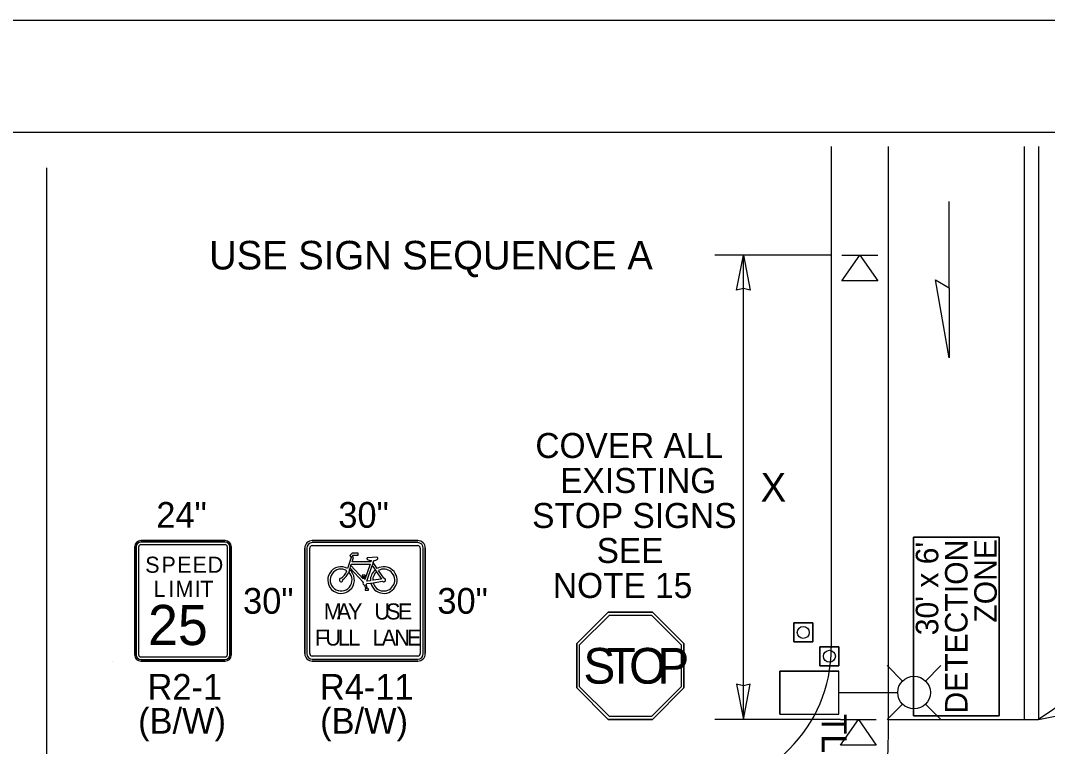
# Model space of a CAD drawing. Extents: x 99979.8 to 100075.7, y 99995 to 100010.7.
# Drawn here: x 100045.178 to 100048.053, y 100008.655 to 100010.687 of the extents above; entities that cross this region are included whole.
import ezdxf

# ---------------------------------------------------------------- set-up
doc = ezdxf.new("R2010")
doc.units = 0
for name, color, linetype in [('RD_ED_ShoulderPavedEdge', 7, 'Continuous'), ('RD_MK_LineDblYellowCenter', 7, 'Continuous'), ('RD_MK_LineEdgeWhite', 7, 'Continuous'), ('RD_MK_LineEdgeWhiteNew', 7, 'Continuous'), ('RD_MK_LineStop', 7, 'Continuous'), ('SH_GI_PlotLimits', 7, 'Continuous'), ('SH_GI_SheetBorder', 7, 'Continuous'), ('TR_SN_ConstructionSigns', 7, 'Continuous'), ('TR_WZ_PortableLightStandard', 7, 'Continuous'), ('TR_WZ_PortableSignMountBlk-Org', 7, 'Continuous'), ('TR_WZ_PortableSignMountBlk-Wht', 7, 'Continuous'), ('TR_WZ_TrafficCone', 7, 'Continuous'), ('TR_WZ_WorkZoneDetails', 7, 'Continuous'), ('TR_WZ_WorkZoneTextCurrent', 7, 'Continuous')]:
    doc.layers.add(name, color=color, linetype=linetype)

msp = doc.modelspace()

# ---------------------------------------------------------------- linework, layer by layer
at = {"layer": 'RD_ED_ShoulderPavedEdge'}
msp.add_lwpolyline([(100047.4475, 100010.335), (100047.4475, 100008.9304)], dxfattribs=at)
msp.add_arc((100047.0475, 100008.9304), 0.4, 270, 0, dxfattribs=at)
at = {"layer": 'RD_MK_LineDblYellowCenter'}
for p, q in [((100047.9875, 100010.335), (100047.9875, 100008.7304)), ((100048.0275, 100010.335), (100048.0275, 100008.7304))]:
    msp.add_line(p, q, dxfattribs=at)
at = {"layer": 'RD_MK_LineEdgeWhite'}
for p, q in [((100047.6075, 100008.9304), (100047.6075, 100010.335)), ((100047.6075, 100008.6904), (100047.6075, 100008.9304))]:
    msp.add_line(p, q, dxfattribs=at)
at = {"layer": 'RD_MK_LineEdgeWhiteNew'}
msp.add_arc((100046.1076, 100008.6984), 1.5, 277.2601, 359.6954, dxfattribs=at)
at = {"layer": 'RD_MK_LineStop'}
msp.add_line((100047.6075, 100008.7304), (100048.0275, 100008.7304), dxfattribs=at)
at = {"layer": 'SH_GI_PlotLimits'}
msp.add_lwpolyline([(100039.0625, 99999.6875), (100056.0625, 99999.6875), (100056.0625, 100010.6875), (100039.0625, 100010.6875)], close=True, dxfattribs=at)
at = {"layer": 'SH_GI_SheetBorder'}
msp.add_line((100040, 100010.375), (100055.75, 100010.375), dxfattribs=at)
at = {"layer": 'TR_SN_ConstructionSigns'}
for p, q in [((100045.5142, 100009.231), (100045.7505, 100009.231)), ((100045.7505, 100009.231), (100045.5142, 100009.231)), ((100045.7505, 100009.231), (100045.5142, 100009.231)), ((100045.7505, 100009.2268), (100045.5142, 100009.2268)), ((100045.9944, 100009.231), (100046.2897, 100009.231)), ((100046.2897, 100009.231), (100045.9944, 100009.231)), ((100046.2897, 100009.231), (100045.9944, 100009.231)), ((100046.2897, 100009.2254), (100045.9944, 100009.2254)), ((100045.4973, 100008.9104), (100045.4973, 100009.2141)), ((100045.4973, 100009.2141), (100045.4973, 100008.9104)), ((100045.4973, 100009.2141), (100045.4973, 100008.9104)), ((100045.5016, 100009.2141), (100045.5016, 100008.9104)), ((100045.5086, 100008.9104), (100045.5086, 100009.2141)), ((100045.5142, 100009.2198), (100045.7505, 100009.2198)), ((100045.7561, 100009.2141), (100045.7561, 100008.9104)), ((100045.7631, 100008.9104), (100045.7631, 100009.2141)), ((100045.7673, 100009.2141), (100045.7673, 100008.9104)), ((100045.7673, 100008.9104), (100045.7673, 100009.2141)), ((100045.7673, 100008.9104), (100045.7673, 100009.2141)), ((100045.9733, 100008.9146), (100045.9733, 100009.2099)), ((100045.9733, 100009.2099), (100045.9733, 100008.9146)), ((100045.9733, 100009.2099), (100045.9733, 100008.9146)), ((100045.9789, 100009.2099), (100045.9789, 100008.9146)), ((100045.9873, 100008.9146), (100045.9873, 100009.2099)), ((100045.9944, 100009.217), (100046.2897, 100009.217)), ((100046.106, 100009.1959), (100046.0991, 100009.1889)), ((100046.1225, 100009.1959), (100046.106, 100009.1959)), ((100046.1225, 100009.1904), (100046.1225, 100009.1959)), ((100046.2967, 100009.2099), (100046.2967, 100008.9146)), ((100046.3051, 100008.9146), (100046.3051, 100009.2099)), ((100046.3108, 100009.2099), (100046.3108, 100008.9146)), ((100046.3108, 100008.9146), (100046.3108, 100009.2099)), ((100046.3108, 100008.9146), (100046.3108, 100009.2099)), ((100046.1037, 100009.1842), (100046.0933, 100009.1531)), ((100046.0991, 100009.1889), (100046.1037, 100009.1842)), ((100046.1025, 100009.1614), (100046.1037, 100009.1652)), ((100046.1037, 100009.1652), (100046.1564, 100009.1652)), ((100046.1059, 100009.1717), (100046.1101, 100009.1842)), ((100046.1586, 100009.1717), (100046.1059, 100009.1717)), ((100046.1061, 100009.1882), (100046.1083, 100009.1904)), ((100046.1101, 100009.1842), (100046.1061, 100009.1882)), ((100046.1083, 100009.1904), (100046.1225, 100009.1904)), ((100046.1564, 100009.1652), (100046.1419, 100009.1219)), ((100046.1744, 100009.1846), (100046.1495, 100009.183)), ((100046.1597, 100009.1751), (100046.1586, 100009.1717)), ((100046.1647, 100009.1694), (100046.1621, 100009.1616)), ((100046.1647, 100009.1694), (100046.1667, 100009.1752)), ((100046.1759, 100009.1529), (100046.1647, 100009.1694)), ((100046.0985, 100009.1496), (100046.0963, 100009.1428)), ((100046.0985, 100009.1496), (100046.1001, 100009.1542)), ((100046.1001, 100009.1542), (100046.1025, 100009.1614)), ((100046.1001, 100009.1542), (100046.1367, 100009.1145)), ((100046.1371, 100009.1237), (100046.1025, 100009.1614)), ((100046.1424, 100009.1344), (100046.1336, 100009.1344)), ((100046.1424, 100009.1311), (100046.1424, 100009.1344)), ((100046.1474, 100009.1173), (100046.1621, 100009.1616)), ((100046.1621, 100009.1616), (100046.1705, 100009.1492)), ((100046.1705, 100009.1492), (100046.1742, 100009.1437)), ((100046.1742, 100009.1437), (100046.188, 100009.1234)), ((100046.1945, 100009.1256), (100046.1796, 100009.1475)), ((100046.1358, 100009.1311), (100046.1371, 100009.1237)), ((100046.1419, 100009.1219), (100046.1402, 100009.1311)), ((100046.1402, 100009.1311), (100046.1424, 100009.1311)), ((100046.141, 100009.1064), (100046.1446, 100009.0956)), ((100046.1493, 100009.0956), (100046.1452, 100009.1077)), ((100046.1469, 100009.1106), (100046.1582, 100009.1123)), ((100046.1573, 100009.1188), (100046.1474, 100009.1173)), ((100046.1582, 100009.1123), (100046.1647, 100009.1132)), ((100046.188, 100009.1234), (100046.1638, 100009.1198)), ((100046.1647, 100009.1132), (100046.191, 100009.1171)), ((100046.1446, 100009.0956), (100046.1428, 100009.0956)), ((100046.1428, 100009.0956), (100046.1428, 100009.0923)), ((100046.1428, 100009.0923), (100046.1516, 100009.0923)), ((100046.1516, 100009.0956), (100046.1493, 100009.0956)), ((100046.1516, 100009.0923), (100046.1516, 100009.0956)), ((100046.8229, 100009.0304), (100046.735, 100008.9426)), ((100046.8229, 100009.0304), (100046.735, 100008.9426)), ((100046.7428, 100008.9393), (100046.8261, 100009.0226)), ((100046.9472, 100009.0304), (100046.8229, 100009.0304)), ((100046.9472, 100009.0304), (100046.8229, 100009.0304)), ((100046.8261, 100009.0226), (100046.9439, 100009.0226)), ((100046.9439, 100009.0226), (100047.0272, 100008.9393)), ((100047.035, 100008.9426), (100046.9472, 100009.0304)), ((100047.035, 100008.9426), (100046.9472, 100009.0304)), ((100046.735, 100008.9426), (100046.735, 100008.8183)), ((100046.735, 100008.9426), (100046.735, 100008.8183)), ((100046.7428, 100008.8216), (100046.7428, 100008.9393)), ((100047.0272, 100008.9393), (100047.0272, 100008.8216)), ((100047.035, 100008.8183), (100047.035, 100008.9426)), ((100047.035, 100008.8183), (100047.035, 100008.9426)), ((100045.7505, 100008.9048), (100045.5142, 100008.9048)), ((100046.2897, 100008.9076), (100045.9944, 100008.9076)), ((100045.5142, 100008.8977), (100045.7505, 100008.8977)), ((100045.7505, 100008.8935), (100045.5142, 100008.8935)), ((100045.5142, 100008.8935), (100045.7505, 100008.8935)), ((100045.5142, 100008.8935), (100045.7505, 100008.8935)), ((100045.9944, 100008.8991), (100046.2897, 100008.8991)), ((100046.2897, 100008.8935), (100045.9944, 100008.8935)), ((100045.9944, 100008.8935), (100046.2897, 100008.8935)), ((100045.9944, 100008.8935), (100046.2897, 100008.8935)), ((100046.735, 100008.8183), (100046.8229, 100008.7304)), ((100046.735, 100008.8183), (100046.8229, 100008.7304)), ((100046.8261, 100008.7383), (100046.7428, 100008.8216)), ((100047.0272, 100008.8216), (100046.9439, 100008.7383)), ((100046.9472, 100008.7304), (100047.035, 100008.8183)), ((100046.9472, 100008.7304), (100047.035, 100008.8183)), ((100046.9439, 100008.7383), (100046.8261, 100008.7383)), ((100046.8229, 100008.7304), (100046.9472, 100008.7304)), ((100046.8229, 100008.7304), (100046.9472, 100008.7304))]:
    msp.add_line(p, q, dxfattribs=at)
for points in [[(100046.1336, 100009.1344), (100046.1336, 100009.1311), (100046.1358, 100009.1311)], [(100046.8229, 100009.0304), (100046.9472, 100009.0304), (100047.035, 100008.9426), (100047.035, 100008.8183), (100046.9472, 100008.7304), (100046.8229, 100008.7304), (100046.735, 100008.8183), (100046.735, 100008.9426), (100046.8229, 100009.0304)]]:
    msp.add_lwpolyline(points, dxfattribs=at)
for centre, radius, start, end in [((100045.5142, 100009.2141), 0.0169, 90, 180), ((100045.5142, 100009.2141), 0.0169, 90, 180), ((100045.5142, 100009.2141), 0.0169, 90, 180), ((100045.5142, 100009.2141), 0.0127, 90, 180), ((100045.7505, 100009.2141), 0.0169, 0, 90), ((100045.7505, 100009.2141), 0.0169, 0, 90), ((100045.7505, 100009.2141), 0.0169, 0, 90), ((100045.7505, 100009.2141), 0.0127, 0, 90), ((100045.9944, 100009.2099), 0.0211, 90, 180), ((100045.9944, 100009.2099), 0.0211, 90, 180), ((100045.9944, 100009.2099), 0.0211, 90, 180), ((100045.9944, 100009.2099), 0.0155, 90, 180), ((100046.2897, 100009.2099), 0.0211, 0, 90), ((100046.2897, 100009.2099), 0.0211, 0, 90), ((100046.2897, 100009.2099), 0.0211, 0, 90), ((100046.2897, 100009.2099), 0.0155, 0, 90), ((100045.5142, 100009.2141), 0.00562, 90, 180), ((100045.7505, 100009.2141), 0.00562, 0, 90), ((100045.9944, 100009.2099), 0.00703, 90, 180), ((100046.2897, 100009.2099), 0.00703, 0, 90), ((100046.1495, 100009.1808), 0.00219, 89.3854, 243.6828), ((100046.1747, 100009.1814), 0.00329, 294.5519, 96.4128), ((100046.075, 100009.1206), 0.0373, 60.5529, 50.868), ((100046.075, 100009.1206), 0.0307, 58.1532, 46.1649), ((100046.1945, 100009.1206), 0.0373, 130.0889, 182.8379), ((100046.1945, 100009.1206), 0.0373, 192.9622, 119.9648), ((100046.1945, 100009.1206), 0.0307, 131.3616, 181.6359), ((100046.1945, 100009.1206), 0.0307, 193.937, 119.0598), ((100046.075, 100009.1206), 0.00493, 105.257, 14.3233), ((100046.1415, 100009.1118), 0.00548, 151.1744, 264.8566), ((100046.1415, 100009.1118), 0.00548, 312.0053, 347.2932), ((100046.1945, 100009.1206), 0.00493, 225.1095, 90.4672), ((100045.5142, 100008.9104), 0.0169, 180, 270), ((100045.5142, 100008.9104), 0.0169, 180, 270), ((100045.5142, 100008.9104), 0.0169, 180, 270), ((100045.5142, 100008.9104), 0.0127, 180, 270), ((100045.5142, 100008.9104), 0.00562, 180, 270), ((100045.7505, 100008.9104), 0.0169, 270, 0), ((100045.7505, 100008.9104), 0.0169, 270, 0), ((100045.7505, 100008.9104), 0.0127, 270, 0), ((100045.7505, 100008.9104), 0.00562, 270, 0), ((100045.7505, 100008.9104), 0.0169, 270, 0), ((100045.9944, 100008.9146), 0.0211, 180, 270), ((100045.9944, 100008.9146), 0.0211, 180, 270), ((100045.9944, 100008.9146), 0.0211, 180, 270), ((100045.9944, 100008.9146), 0.0155, 180, 270), ((100045.9944, 100008.9146), 0.00703, 180, 270), ((100046.2897, 100008.9146), 0.0211, 270, 0), ((100046.2897, 100008.9146), 0.0211, 270, 0), ((100046.2897, 100008.9146), 0.0155, 270, 0), ((100046.2897, 100008.9146), 0.00703, 270, 0), ((100046.2897, 100008.9146), 0.0211, 270, 0)]:
    msp.add_arc(centre, radius, start, end, dxfattribs=at)
for centre, major_axis, ratio, start_param, end_param in [((100046.1627, 100009.1859), (-0.0186, 0), 0.588235, 0.686048, 1.410588), ((100046.1627, 100009.1859), (-0.0186, 0), 0.588235, 1.786993, 2.401245), ((100046.0799, 100009.1414), (-0.0105, -0.0158), 0.413554, 0.494612, 2.170849), ((100046.0799, 100009.1414), (-0.014, -0.021), 0.55814, 0.868091, 1.989998)]:
    msp.add_ellipse(centre, major_axis=major_axis, ratio=ratio, start_param=start_param, end_param=end_param, dxfattribs=at)
at = {"layer": 'TR_WZ_PortableLightStandard'}
for p, q in [((100047.6468, 100008.8378), (100047.6037, 100008.8809)), ((100047.7115, 100008.8378), (100047.7546, 100008.8809)), ((100047.303, 100008.8654), (100047.469, 100008.8654)), ((100047.303, 100008.7454), (100047.303, 100008.8654)), ((100047.469, 100008.8654), (100047.303, 100008.8654)), ((100047.469, 100008.7454), (100047.469, 100008.8654)), ((100047.469, 100008.8054), (100047.6334, 100008.8054)), ((100047.6468, 100008.773), (100047.6037, 100008.7301)), ((100047.7115, 100008.773), (100047.7546, 100008.7301)), ((100047.303, 100008.7454), (100047.469, 100008.7454)), ((100047.303, 100008.7454), (100047.469, 100008.7454))]:
    msp.add_line(p, q, dxfattribs=at)
for points in [[(100047.303, 100008.8654), (100047.303, 100008.8054), (100047.303, 100008.7454)], [(100047.469, 100008.7454), (100047.469, 100008.8054), (100047.469, 100008.8654)]]:
    msp.add_lwpolyline(points, dxfattribs=at)
msp.add_circle((100047.6792, 100008.8055), 0.0457, dxfattribs=at)
msp.add_circle((100047.6792, 100008.8055), 0.0457, dxfattribs=at)
at = {"layer": 'TR_WZ_PortableSignMountBlk-Org'}
msp.add_line((100047.4775, 100010.0304), (100047.5775, 100010.0304), dxfattribs=at)
msp.add_lwpolyline([(100047.5274, 100010.0304), (100047.5775, 100009.9586), (100047.4775, 100009.9586)], close=True, dxfattribs=at)
at = {"layer": 'TR_WZ_PortableSignMountBlk-Wht'}
msp.add_line((100047.4734, 100008.7304), (100047.5734, 100008.7304), dxfattribs=at)
msp.add_lwpolyline([(100047.5233, 100008.7304), (100047.5734, 100008.6586), (100047.4734, 100008.6586)], close=True, dxfattribs=at)
at = {"layer": 'TR_WZ_TrafficCone'}
for points in [[(100047.3956, 100009.0004), (100047.3956, 100008.9471), (100047.3423, 100008.9471), (100047.3423, 100009.0004), (100047.3956, 100009.0004)], [(100047.3423, 100009.0004), (100047.3423, 100008.9471), (100047.3956, 100008.9471), (100047.3956, 100009.0004), (100047.3423, 100009.0004)], [(100047.469, 100008.9338), (100047.469, 100008.8804), (100047.4156, 100008.8804), (100047.4156, 100008.9338), (100047.469, 100008.9338)], [(100047.4156, 100008.9338), (100047.4156, 100008.8804), (100047.469, 100008.8804), (100047.469, 100008.9338), (100047.4156, 100008.9338)]]:
    msp.add_lwpolyline(points, dxfattribs=at)
for centre in [(100047.369, 100008.9738), (100047.4423, 100008.9071)]:
    msp.add_circle(centre, 0.0167, dxfattribs=at)
at = {"layer": 'TR_WZ_WorkZoneDetails'}
for p, q in [((100045.25, 100010.275), (100045.25, 100001.7859)), ((100047.778, 100009.9393), (100047.778, 100010.1804)), ((100047.4475, 100010.0304), (100047.1216, 100010.0304)), ((100047.2016, 100008.7304), (100047.2016, 100010.0304)), ((100046.735, 100008.9426), (100046.8229, 100009.0304)), ((100046.8229, 100009.0304), (100046.735, 100008.9426)), ((100046.8229, 100009.0304), (100046.9472, 100009.0304)), ((100046.9472, 100009.0304), (100046.8229, 100009.0304)), ((100046.8229, 100009.0304), (100046.8229, 100009.0304)), ((100046.9472, 100009.0304), (100047.035, 100008.9426)), ((100047.035, 100008.9426), (100046.9472, 100009.0304)), ((100046.735, 100008.9426), (100046.735, 100008.9426)), ((100046.735, 100008.8183), (100046.735, 100008.9426)), ((100046.735, 100008.9426), (100046.735, 100008.8183)), ((100047.035, 100008.9426), (100047.035, 100008.9426)), ((100047.035, 100008.9426), (100047.035, 100008.8183)), ((100047.035, 100008.8183), (100047.035, 100008.9426)), ((100045.4336, 100008.8935), (100045.4336, 100008.8935)), ((100046.735, 100008.8183), (100046.735, 100008.8183)), ((100046.8229, 100008.7304), (100046.735, 100008.8183)), ((100046.735, 100008.8183), (100046.8229, 100008.7304)), ((100047.035, 100008.8183), (100046.9472, 100008.7304)), ((100046.9472, 100008.7304), (100047.035, 100008.8183)), ((100047.035, 100008.8183), (100047.035, 100008.8183)), ((100046.8229, 100008.7304), (100046.8229, 100008.7304)), ((100046.9472, 100008.7304), (100046.8229, 100008.7304)), ((100046.8229, 100008.7304), (100046.9472, 100008.7304)), ((100046.9472, 100008.7304), (100046.9472, 100008.7304)), ((100047.4734, 100008.7304), (100047.1216, 100008.7304))]:
    msp.add_line(p, q, dxfattribs=at)
for points in [[(100047.2016, 100010.0304), (100047.2208, 100009.9322), (100047.2016, 100009.9367), (100047.1823, 100009.9322)], [(100047.778, 100009.7428), (100047.7394, 100009.9616), (100047.778, 100009.9393)], [(100047.2016, 100008.7304), (100047.2208, 100008.8287), (100047.2016, 100008.8242), (100047.1823, 100008.8287)], [(100048.0275, 100008.7304), (100048.1258, 100008.7499), (100048.1143, 100008.766), (100048.1112, 100008.7856)]]:
    msp.add_lwpolyline(points, close=True, dxfattribs=at)
for points in [[(100047.6775, 100009.2404), (100047.6775, 100008.7404), (100047.9175, 100008.7404), (100047.9175, 100009.2404), (100047.6775, 100009.2404)], [(100047.9175, 100009.2404), (100047.9175, 100008.7404), (100047.6775, 100008.7404), (100047.6775, 100009.2404), (100047.9175, 100009.2404)]]:
    msp.add_lwpolyline(points, dxfattribs=at)

# ---------------------------------------------------------------- texts
at = {"layer": 'TR_SN_ConstructionSigns'}
for s, height, p in [('COVER ALL', 0.07, (100046.619, 100009.4624)), ('EXISTING', 0.07, (100046.6885, 100009.3644)), ('STOP SIGNS', 0.07, (100046.61, 100009.2664)), ('SEE', 0.07, (100046.7906, 100009.1684)), ('S', 0.045, (100045.5266, 100009.141)), ('P', 0.045, (100045.572, 100009.141)), ('E', 0.045, (100045.6161, 100009.141)), ('E', 0.045, (100045.6589, 100009.141)), ('D', 0.045, (100045.7016, 100009.141)), ('NOTE 15', 0.07, (100046.6682, 100009.0704)), ('L', 0.045, (100045.55, 100009.0735)), ('I', 0.045, (100045.5914, 100009.0735)), ('M', 0.045, (100045.6112, 100009.0735)), ('I', 0.045, (100045.6652, 100009.0735)), ('T', 0.045, (100045.6809, 100009.0735)), ('25', 0.1125, (100045.5345, 100008.9385)), ('M', 0.045, (100046.027, 100009.0102)), ('A', 0.045, (100046.063, 100009.0102)), ('Y', 0.045, (100046.0945, 100009.0102)), ('U', 0.045, (100046.1683, 100009.0102)), ('S', 0.045, (100046.2012, 100009.0102)), ('E', 0.045, (100046.234, 100009.0102)), ('F', 0.045, (100046.0018, 100008.9371)), ('U', 0.045, (100046.0311, 100008.9371)), ('L', 0.045, (100046.0662, 100008.9371)), ('L', 0.045, (100046.0954, 100008.9371)), ('L', 0.045, (100046.1634, 100008.9371)), ('A', 0.045, (100046.189, 100008.9371)), ('N', 0.045, (100046.2241, 100008.9371)), ('E', 0.045, (100046.2592, 100008.9371))]:
    msp.add_text(s, height=height, dxfattribs=at).set_placement(p)
for s, p in [('24"', (100045.5576, 100009.267)), ('30"', (100046.0673, 100009.267)), ('30"', (100045.8006, 100009.0263)), ('30"', (100046.3446, 100009.0263)), ('R2-1', (100045.5332, 100008.7855)), ('R4-11', (100046.0158, 100008.7855)), ('(B/W)', (100045.5068, 100008.6904)), ('(B/W)', (100046.0165, 100008.6904))]:
    msp.add_text(s, height=0.072, rotation=360, dxfattribs=at).set_placement(p)
at = {"layer": 'TR_WZ_PortableLightStandard'}
msp.add_text('TL', height=0.07, rotation=270, dxfattribs=at).set_placement((100047.421, 100008.7455))
at = {"layer": 'TR_WZ_WorkZoneDetails'}
for s, p in [("30' x 6'", (100047.7471, 100008.966)), ('DETECTION', (100047.829, 100008.7468)), ('ZONE', (100047.9109, 100009.0012))]:
    msp.add_text(s, height=0.063, rotation=90, dxfattribs=at).set_placement(p)
for s, p in [('S', (100046.7535, 100008.8304)), ('T', (100046.8185, 100008.8304)), ('O', (100046.8815, 100008.8304)), ('P', (100046.9605, 100008.8304))]:
    msp.add_text(s, height=0.1, dxfattribs=at).set_placement(p)
at = {"layer": 'TR_WZ_WorkZoneTextCurrent'}
for s, p in [('USE SIGN SEQUENCE A', (100045.7054, 100009.9904)), ('X', (100047.2498, 100009.3404))]:
    msp.add_text(s, height=0.08, dxfattribs=at).set_placement(p)

doc.saveas('drawing.dxf')
